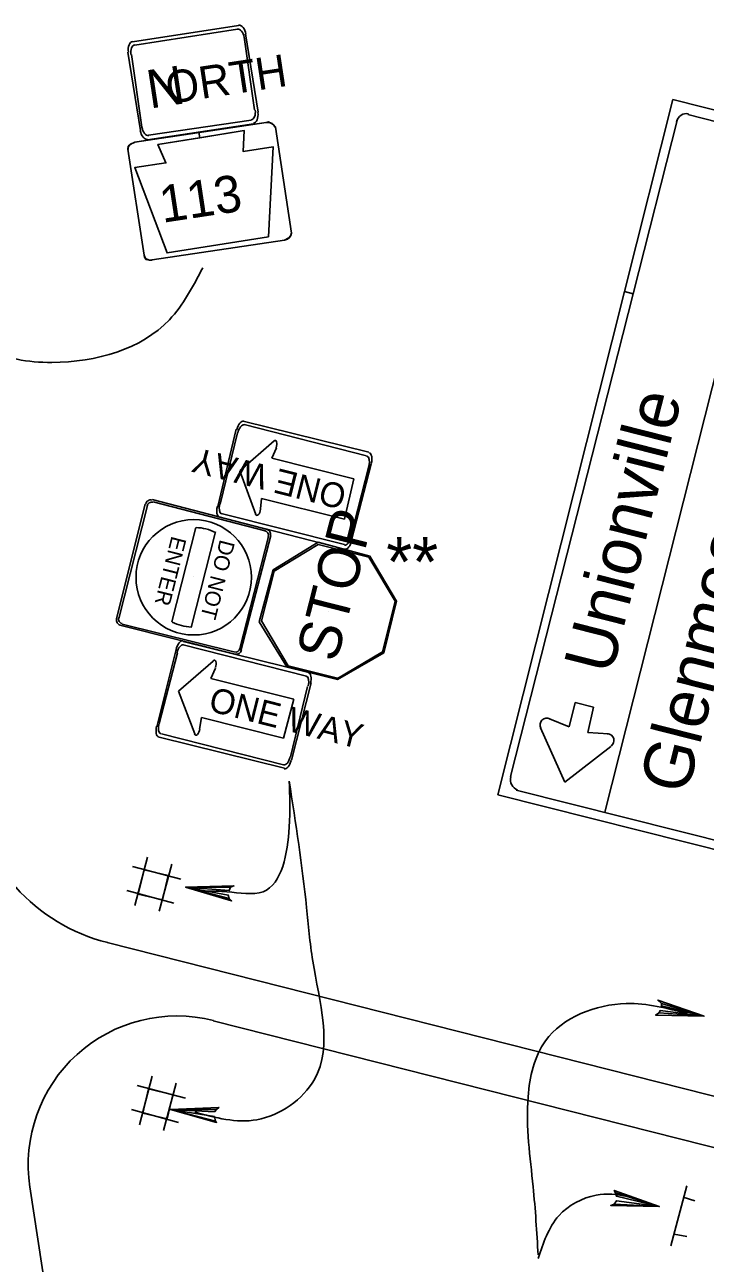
# Model space of a CAD drawing. Extents: x 644898 to 648326, y 298294 to 300670.
# Drawn here: x 647835.4 to 647909.2, y 300456 to 300590.2 of the extents above; entities that cross this region are included whole.
import ezdxf

# ---------------------------------------------------------------- set-up
doc = ezdxf.new("R2010")
doc.units = 0
doc.layers.add('2', color=7, linetype='Continuous')

msp = doc.modelspace()

# ---------------------------------------------------------------- linework, layer by layer
at = {"layer": '2'}
for p, q in [((647847.07, 300588.37), (647858.57, 300590.12)), ((647847.32, 300587.99), (647858.45, 300589.74)), ((647859.2, 300588.87), (647860.32, 300580.99)), ((647859.32, 300589.24), (647860.7, 300580.74)), ((647847.95, 300578.74), (647846.57, 300587.24)), ((647848.07, 300579.12), (647846.95, 300586.99)), ((647853.7, 300583.99), (647853.7, 300583.99)), ((647900.45, 300561.3), (647905.7, 300582.12)), ((647905.7, 300582.12), (647939.45, 300573.49)), ((647906.2, 300579.99), (647901.38, 300561.06)), ((647937.2, 300572.87), (647907.32, 300580.49)), ((647847.32, 300577.49), (647861.57, 300579.62)), ((647861.57, 300579.62), (647847.32, 300577.49)), ((647860.2, 300579.49), (647848.7, 300577.74)), ((647859.95, 300579.87), (647848.82, 300578.24)), ((647859.2, 300578.74), (647854.57, 300577.99)), ((647859.07, 300576.49), (647859.2, 300578.74)), ((647862.57, 300579.12), (647864.32, 300567.62)), ((647864.32, 300567.62), (647862.57, 300579.12)), ((647847.32, 300577.49), (647847.32, 300577.49)), ((647854.57, 300577.99), (647849.82, 300577.24)), ((647898.32, 300504.87), (647916.82, 300578.12)), ((647848.32, 300565.24), (647846.57, 300576.74)), ((647846.57, 300576.74), (647848.32, 300565.24)), ((647849.82, 300577.24), (647850.7, 300575.24)), ((647862.32, 300576.99), (647859.07, 300576.49)), ((647861.82, 300567.24), (647862.32, 300576.99)), ((647850.7, 300575.24), (647847.32, 300574.74)), ((647847.32, 300574.74), (647850.82, 300565.49)), ((647855.45, 300572.12), (647855.45, 300572.12)), ((647855.45, 300572.12), (647855.45, 300572.12)), ((647863.57, 300566.87), (647849.2, 300564.74)), ((647849.2, 300564.74), (647863.57, 300566.87)), ((647850.82, 300565.49), (647861.82, 300567.24)), ((647886.7, 300506.74), (647900.45, 300561.3)), ((647901.38, 300561.06), (647900.45, 300561.3)), ((647900.45, 300561.3), (647901.38, 300561.06)), ((647901.38, 300561.06), (647888.07, 300508.74)), ((647859.07, 300547.24), (647872.7, 300543.87)), ((647859.2, 300546.87), (647872.45, 300543.49)), ((647856.32, 300537.99), (647858.32, 300546.37)), ((647856.57, 300538.24), (647858.45, 300545.99)), ((647858.7, 300541.87), (647862.45, 300545.12)), ((647862.7, 300544.37), (647862.2, 300543.24)), ((647862.2, 300543.24), (647871.07, 300540.99)), ((647872.95, 300542.62), (647870.82, 300534.37)), ((647860.45, 300537.12), (647858.7, 300541.87)), ((647872.7, 300542.37), (647870.7, 300534.62)), ((647864.57, 300540.37), (647864.57, 300540.37)), ((647871.07, 300540.99), (647870.07, 300536.62)), ((647849.2, 300538.74), (647861.7, 300535.49)), ((647849.32, 300538.49), (647861.45, 300535.37)), ((647861.07, 300538.87), (647860.95, 300537.74)), ((647870.07, 300536.62), (647861.07, 300538.87)), ((647845.32, 300525.87), (647848.45, 300538.24)), ((647845.57, 300525.87), (647848.7, 300538.12)), ((647870.07, 300533.87), (647856.7, 300537.24)), ((647906.57, 300537.24), (647906.57, 300537.24)), ((647851.32, 300525.49), (647853.95, 300535.74)), ((647870.07, 300533.37), (647856.45, 300536.87)), ((647856.07, 300535.24), (647853.45, 300524.87)), ((647861.82, 300534.74), (647858.7, 300522.62)), ((647862.07, 300534.87), (647858.82, 300522.37)), ((647853.7, 300530.37), (647853.7, 300530.37)), ((647868.32, 300526.62), (647868.32, 300526.62)), ((647858.2, 300521.99), (647845.7, 300525.12)), ((647858.07, 300522.24), (647845.95, 300525.24)), ((647849.7, 300514.12), (647851.82, 300522.49)), ((647852.57, 300523.37), (647866.2, 300519.99)), ((647852.57, 300522.99), (647865.95, 300519.62)), ((647849.95, 300514.49), (647851.95, 300522.12)), ((647855.82, 300521.24), (647852.07, 300517.99)), ((647855.57, 300519.37), (647856.07, 300520.49)), ((647864.57, 300517.12), (647855.57, 300519.37)), ((647866.07, 300518.49), (647864.2, 300510.87)), ((647866.45, 300518.87), (647864.32, 300510.49)), ((647852.07, 300517.99), (647853.82, 300513.37)), ((647863.45, 300512.87), (647864.57, 300517.12)), ((647858.07, 300516.49), (647858.07, 300516.49)), ((647858.07, 300516.49), (647858.07, 300516.49)), ((647894.45, 300514.12), (647895.07, 300516.74)), ((647895.07, 300516.74), (647894.45, 300514.12)), ((647895.07, 300516.74), (647897.07, 300516.24)), ((647897.07, 300516.24), (647895.07, 300516.74)), ((647897.07, 300516.24), (647896.45, 300513.49)), ((647896.45, 300513.49), (647897.07, 300516.24)), ((647854.32, 300513.87), (647854.57, 300515.12)), ((647854.57, 300515.12), (647863.45, 300512.87)), ((647892.32, 300514.99), (647894.45, 300514.12)), ((647894.45, 300514.12), (647892.32, 300514.99)), ((647863.57, 300509.62), (647849.95, 300512.99)), ((647863.45, 300509.99), (647850.2, 300513.37)), ((647893.95, 300508.12), (647891.32, 300513.99)), ((647891.32, 300513.99), (647893.95, 300508.12)), ((647896.45, 300513.49), (647898.7, 300513.37)), ((647898.7, 300513.37), (647896.45, 300513.49)), ((647898.57, 300513.37), (647898.7, 300513.37)), ((647898.95, 300511.99), (647893.95, 300508.12)), ((647893.95, 300508.12), (647898.95, 300511.99)), ((647920.45, 300498.24), (647886.7, 300506.74)), ((647888.7, 300507.24), (647918.57, 300499.74)), ((647847.32, 300494.74), (647848.7, 300499.99)), ((647852.32, 300497.62), (647847.07, 300498.99)), ((647849.95, 300494.12), (647851.32, 300499.24)), ((647851.57, 300494.99), (647846.45, 300496.37)), ((647989.82, 300453.87), (647844.32, 300490.74)), ((648029.82, 300438.24), (647855.82, 300482.24)), ((647847.82, 300470.99), (647849.2, 300476.24)), ((647850.45, 300470.37), (647851.82, 300475.49)), ((647852.82, 300473.87), (647847.57, 300475.24)), ((647852.07, 300471.24), (647846.95, 300472.62)), ((647835.95, 300464.24), (647846.95, 300391.87)), ((647907.2, 300464.37), (647905.45, 300457.87)), ((647906.82, 300463.12), (647908.07, 300462.74)), ((647905.82, 300459.12), (647907.2, 300458.87))]:
    msp.add_line(p, q, dxfattribs=at)
for points in [[(647847.32, 300577.49), (647846.87, 300577.27), (647846.61, 300577.04), (647846.57, 300576.74), (647848.32, 300565.24), (647848.53, 300564.78), (647848.96, 300564.7), (647849.2, 300564.74), (647863.57, 300566.87), (647864.04, 300567.11), (647864.25, 300567.37), (647864.32, 300567.62), (647862.57, 300579.12), (647862.33, 300579.42), (647861.83, 300579.69), (647861.57, 300579.62), (647854.27, 300578.59), (647854.38, 300577.97), (647859.2, 300578.74), (647859.07, 300576.49), (647862.32, 300576.99), (647861.82, 300567.24), (647850.82, 300565.49), (647847.32, 300574.74), (647850.7, 300575.24), (647849.82, 300577.24), (647854.38, 300577.97), (647854.26, 300578.58)], [(647848.32, 300498.62), (647850.95, 300497.99), (647850.32, 300495.37), (647847.7, 300495.99)], [(647848.82, 300474.87), (647851.45, 300474.24), (647850.82, 300471.62), (647848.2, 300472.24)]]:
    msp.add_lwpolyline(points, close=True, dxfattribs=at)
for points in [[(647869.32, 300519.24), (647874.32, 300522.12), (647875.7, 300527.74), (647872.82, 300532.62), (647867.2, 300534.12), (647862.32, 300531.12), (647860.82, 300525.49), (647863.82, 300520.62), (647869.32, 300519.24)], [(647869.32, 300519.37), (647874.2, 300522.24), (647875.57, 300527.74), (647872.7, 300532.49), (647867.2, 300533.87), (647862.45, 300530.99), (647861.07, 300525.62), (647863.95, 300520.74), (647869.45, 300519.37)], [(647857.57, 300495.49), (647857.45, 300495.87), (647852.82, 300496.74), (647857.57, 300495.49), (647857.82, 300495.24), (647852.82, 300496.74), (647857.57, 300496.37), (647857.7, 300496.74), (647852.82, 300496.74), (647858.07, 300496.87), (647857.7, 300496.74)], [(647904.45, 300484.12), (647904.45, 300483.87), (647909.07, 300482.74), (647904.45, 300484.12), (647904.07, 300484.49), (647909.07, 300482.74), (647904.32, 300483.37), (647904.2, 300483.12), (647909.07, 300482.74), (647903.82, 300482.87), (647904.2, 300483.12)], [(647856.07, 300471.37), (647855.95, 300471.87), (647851.2, 300472.62), (647856.07, 300471.37), (647856.2, 300471.24), (647851.2, 300472.62), (647855.95, 300472.37), (647856.2, 300472.62), (647851.2, 300472.62), (647856.45, 300472.87), (647856.2, 300472.62)], [(647899.45, 300463.62), (647899.57, 300463.24), (647904.2, 300462.12), (647899.45, 300463.62), (647899.32, 300463.87), (647904.2, 300462.12), (647899.57, 300462.74), (647899.32, 300462.37), (647904.2, 300462.12), (647898.95, 300462.24), (647899.32, 300462.37)]]:
    msp.add_lwpolyline(points, dxfattribs=at)
msp.add_circle((647853.71, 300530.33), 6.26, dxfattribs=at)
for centre, radius, start, end in [((647849.04, 300538.15), 0.559, 75.7794, 165.7794), ((647849.16, 300537.95), 0.517, 75.7794, 165.7794), ((647853.7, 300530.28), 5.45, 64.3582, 87.2006), ((647861.3, 300534.87), 0.517, 345.7794, 75.7794), ((647861.5, 300534.99), 0.559, 345.7794, 75.7794), ((647845.88, 300525.68), 0.559, 165.7794, 255.7794), ((647846.08, 300525.8), 0.517, 165.7794, 255.7794), ((647853.73, 300530.38), 5.45, 244.3582, 267.2006), ((647858.22, 300522.73), 0.517, 255.7794, 345.7794), ((647858.34, 300522.53), 0.559, 255.7794, 345.7794), ((647892.02, 300514.33), 0.745, 64.0264, 207.9331), ((647892.02, 300514.33), 0.745, 64.0264, 207.9331), ((647898.55, 300512.63), 0.745, 305.638, 86.3035), ((647898.55, 300512.63), 0.745, 305.638, 86.3035), ((647849.33, 300510.27), 20.16, 188.6538, 255.7794), ((647851.89, 300466.65), 16.13, 75.7793, 188.6538)]:
    msp.add_arc(centre, radius, start, end, dxfattribs=at)
for centre, major_axis, ratio, start_param, end_param in [((647858.59, 300588.76), (-0.15, 0.983), 0.6, 4.712389, 6.283185), ((647858.74, 300589.1), (-0.16, 1.06), 0.6, 4.712389, 6.283185), ((647847.26, 300587.35), (0.16, -1.06), 0.6, 3.141593, 4.712389), ((647847.49, 300587.07), (0.15, -0.983), 0.6, 3.141593, 4.712389), ((647859.79, 300580.88), (-0.15, 0.983), 0.6, 3.141593, 4.712389), ((647860.03, 300580.6), (-0.16, 1.06), 0.6, 3.141593, 4.712389), ((647907.1, 300579.41), (-0.29, -1.16), 0.890186, 3.141593, 4.712389), ((647848.55, 300578.85), (0.16, -1.06), 0.6, 4.712389, 6.283185), ((647848.69, 300579.19), (0.15, -0.983), 0.6, 4.712389, 6.283185), ((647861.72, 300578.99), (-0.797, -0.121), 0.8, 3.141593, 4.712389), ((647861.72, 300578.99), (-0.797, -0.121), 0.8, 3.141593, 4.712389), ((647847.38, 300576.81), (-0.797, -0.121), 0.8, 4.712389, 6.283185), ((647847.38, 300576.81), (-0.797, -0.121), 0.8, 4.712389, 6.283185), ((647863.47, 300567.51), (0.797, 0.121), 0.8, 4.712389, 6.283185), ((647863.47, 300567.51), (0.797, 0.121), 0.8, 4.712389, 6.283185), ((647849.12, 300565.33), (0.797, 0.121), 0.8, 3.141593, 4.712389), ((647849.12, 300565.33), (0.797, 0.121), 0.8, 3.141593, 4.712389), ((647858.87, 300546.22), (-0.26, -1.04), 0.4667, 3.141593, 4.712389), ((647858.94, 300545.87), (-0.244, -0.964), 0.4667, 3.141593, 4.712389), ((647862.44, 300544.59), (0.142, 0.56), 0.4667, 4.423888, 6.899163), ((647872.49, 300542.77), (0.26, 1.04), 0.4667, 4.712389, 6.283185), ((647872.26, 300542.5), (0.244, 0.964), 0.4667, 4.712389, 6.283185), ((647856.76, 300537.88), (-0.26, -1.04), 0.4667, 4.712389, 6.283185), ((647856.98, 300538.16), (-0.244, -0.964), 0.4667, 4.712389, 6.283185), ((647860.67, 300537.6), (0.142, 0.56), 0.4667, 2.525615, 5.00089), ((647870.31, 300534.78), (0.244, 0.964), 0.4667, 3.141593, 4.712389), ((647870.37, 300534.43), (0.26, 1.04), 0.4667, 3.141593, 4.712389), ((647852.28, 300522.39), (-0.26, -1.04), 0.4667, 3.141593, 4.712389), ((647852.35, 300522.04), (-0.244, -0.964), 0.4667, 3.141593, 4.712389), ((647855.86, 300520.77), (0.142, 0.56), 0.4667, 4.423888, 6.899163), ((647865.68, 300518.66), (0.244, 0.964), 0.4667, 4.712389, 6.283185), ((647865.9, 300518.94), (0.26, 1.04), 0.4667, 4.712389, 6.283185), ((647850.39, 300514.32), (-0.244, -0.964), 0.4667, 4.712389, 6.283185), ((647850.17, 300514.05), (-0.26, -1.04), 0.4667, 4.712389, 6.283185), ((647854.08, 300513.78), (0.142, 0.56), 0.4667, 2.525615, 5.00089), ((647863.72, 300510.95), (0.244, 0.964), 0.4667, 3.141593, 4.712389), ((647863.79, 300510.6), (0.26, 1.04), 0.4667, 3.141593, 4.712389), ((647889.14, 300508.46), (-0.29, -1.16), 0.890186, 4.712389, 6.283185)]:
    msp.add_ellipse(centre, major_axis=major_axis, ratio=ratio, start_param=start_param, end_param=end_param, dxfattribs=at)
for points in [[(647854.7, 300563.87), (647851.07, 300558.24), (647838.32, 300553.62), (647831.32, 300555.24), (647826.45, 300564.24)], [(647864.07, 300508.24), (647865.95, 300494.54), (647866.62, 300488.73), (647866.8, 300475.89), (647860.57, 300471.53), (647853.82, 300472.37)], [(647864.07, 300508.24), (647864.07, 300503.24), (647861.23, 300496.24), (647857.32, 300496.24), (647855.18, 300496.3)], [(647891.07, 300456.87), (647890.53, 300464.27), (647889.98, 300474.02), (647891.86, 300480.07), (647900.63, 300484.12), (647907.23, 300483.04)], [(647891.07, 300456.49), (647893.32, 300461.12), (647897.36, 300463.35), (647904.2, 300462.12)]]:
    msp.add_spline(points, degree=3, dxfattribs=at)

# ---------------------------------------------------------------- texts
for s, height, rotation, p in [('ORTH', 3.487, 8.6538, (647850.95, 300581.62)), ('N', 4.16, 8.6525, (647848.95, 300581.12)), ('113', 4, 8.6536, (647850.32, 300568.74)), ('Unionville', 5.375, 75.7788, (647899.03, 300519.63)), ('ONE WAY', 2.687, 165.779, (647870.45, 300540.24)), ('Glenmoore   ', 5.3752, 75.7788, (647907.22, 300506.62)), ('STOP', 4.541, 75.7795, (647869.2, 300520.99)), ('ENTER', 1.677, 255.781, (647851.32, 300534.87)), ('**', 5.417, 359.8589, (647874.58, 300529.29)), ('DO NOT', 1.677, 255.7793, (647856.57, 300534.49)), ('ONE WAY', 2.687, 345.779, (647855.2, 300515.87))]:
    msp.add_text(s, height=height, rotation=rotation, dxfattribs=at).set_placement(p)

doc.saveas('drawing.dxf')
